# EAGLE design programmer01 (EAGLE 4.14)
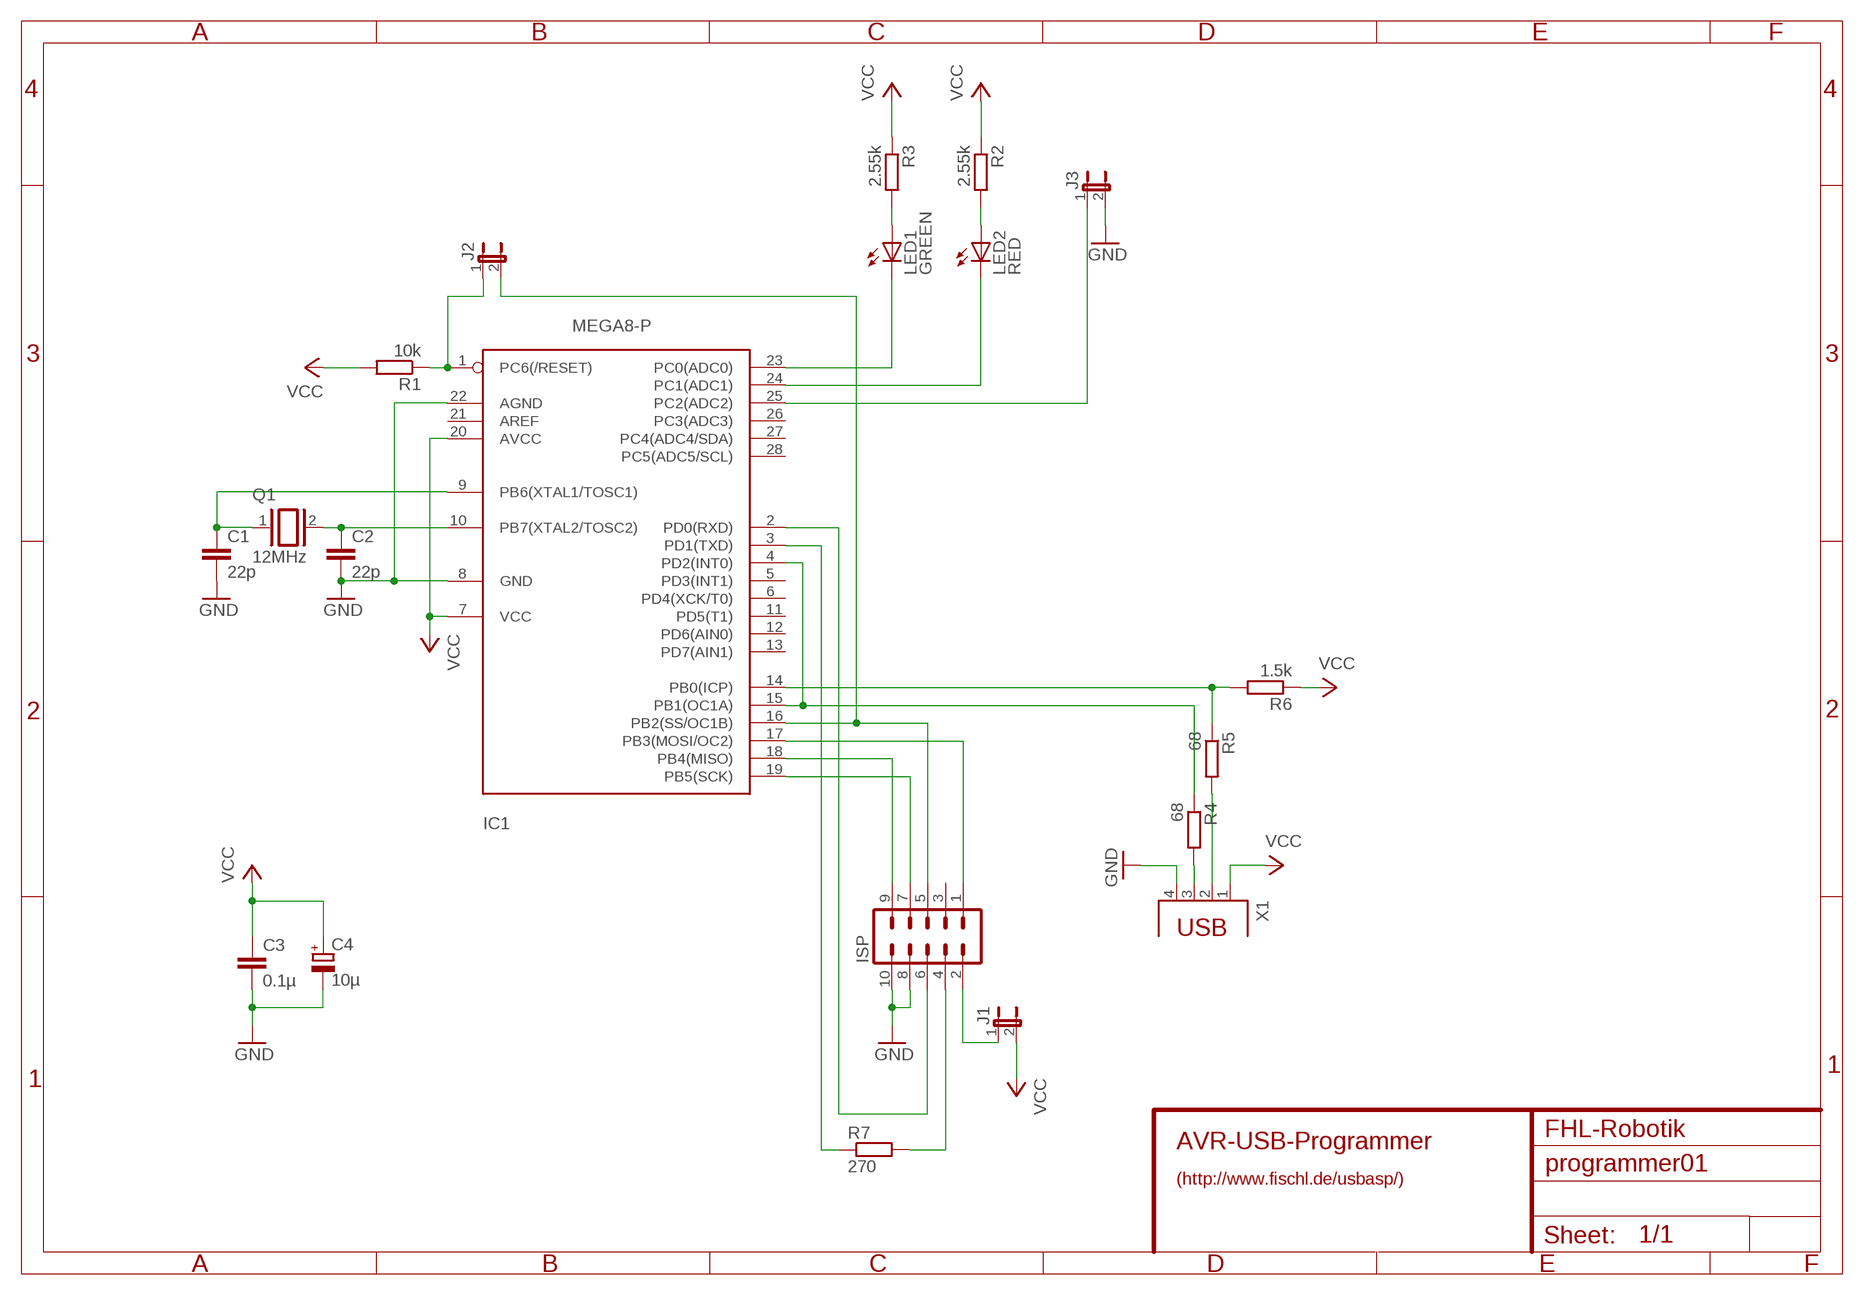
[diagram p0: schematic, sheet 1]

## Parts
C1  22p  C-EU025-025X050  [C025-025X050]
C2  22p  C-EU025-025X050  [C025-025X050]
C3  0.1µ  C-EU025-025X050  [C025-025X050]
C4  10µ  CPOL-EUE2.5-5  [E2,5-5]
IC1  MEGA8-P  [DIL28-3]
ISP  MA05-2  [MA05-2]
J1  JP1E  [JP1]
J2  JP1E  [JP1]
J3  JP1E  [JP1]
LED1  GREEN  LED3MM  [LED3MM]
LED2  RED  LED3MM  [LED3MM]
Q1  12MHz  XTAL/S  [QS]
R1  10k  R-EU_0207/7  [0207/7]
R2  2.55k  R-EU_0207/7  [0207/7]
R3  2.55k  R-EU_0207/7  [0207/7]
R4  68  R-EU_0207/7  [0207/7]
R5  68  R-EU_0207/7  [0207/7]
R6  1.5k  R-EU_0207/7  [0207/7]
R7  270  R-EU_0207/7  [0207/7]
X1  PN61729  [PN61729]

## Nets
GND: C1.2 C2.2 C3.2 C4.- IC1.8(GND) IC1.22(AGND) ISP.8 ISP.10 J3.2 X1.4
N$1: C2.1 IC1.10(PB7(XTAL2/TOSC2)) Q1.2
N$2: C1.1 IC1.9(PB6(XTAL1/TOSC1)) Q1.1
N$3: IC1.1(PC6(/RESET)) J2.1 R1.1
N$4: IC1.16(PB2(SS/OC1B)) ISP.5 J2.2
N$5: IC1.24(PC1(ADC1)) LED2.K(C)
N$6: LED2.A R2.2
N$7: LED1.A R3.2
N$8: IC1.23(PC0(ADC0)) LED1.K(C)
N$9: IC1.4(PD2(INT0)) IC1.15(PB1(OC1A)) R4.1
N$10: R4.2 X1.3
N$11: R5.2 X1.2
N$12: IC1.14(PB0(ICP)) R5.1 R6.2
N$13: IC1.25(PC2(ADC2)) J3.1
N$14: IC1.17(PB3(MOSI/OC2)) ISP.1
N$15: IC1.19(PB5(SCK)) ISP.7
N$16: IC1.18(PB4(MISO)) ISP.9
N$17: ISP.2 J1.1
N$19: IC1.3(PD1(TXD)) R7.1
N$21: IC1.2(PD0(RXD)) ISP.6
N$22: ISP.4 R7.2
VCC: C3.1 C4.+ IC1.7(VCC) IC1.20(AVCC) J1.2 R1.2 R2.1 R3.1 R6.1 X1.1
Unconnected: IC1.5(PD3(INT1)) IC1.6(PD4(XCK/T0)) IC1.11(PD5(T1)) IC1.12(PD6(AIN0)) IC1.13(PD7(AIN1)) IC1.21(AREF) IC1.26(PC3(ADC3)) IC1.27(PC4(ADC4/SDA)) IC1.28(PC5(ADC5/SCL)) ISP.3

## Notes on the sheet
- FHL-Robotik
- AVR-USB-Programmer
- (http://www.fischl.de/usbasp/)

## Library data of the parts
C1-C3 = rcl:C-EU: CAPACITOR, European symbol
C4 = rcl:CPOL-EU: POLARIZED CAPACITOR, European symbol
IC1 = avr:MEGA8-P: MICROCONTROLLER 8 Kbytes FLASH 1 kbytes SRAM 512 bytes EEPROM USART 4-channel 10 bit ADC 2-channel 8 bit ADC
ISP = con-lstb:MA05-2: PIN HEADER
J1-J3 = jumper:JP1E: JUMPER
LED1 LED2 = led:LED: LED
Q1 = special:XTAL/S: CRYSTAL
R1-R7 = rcl:R-EU_: RESISTOR, European symbol
X1 = con-berg:PN61729: BERG USB connector

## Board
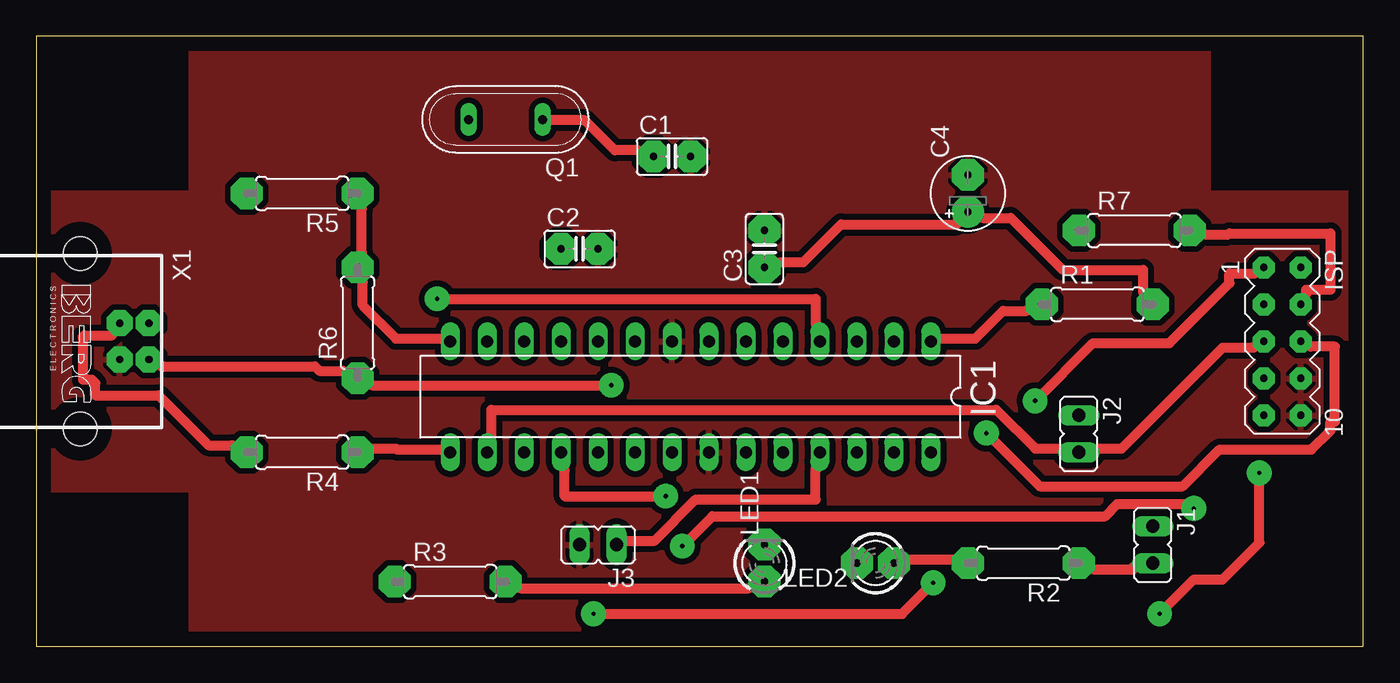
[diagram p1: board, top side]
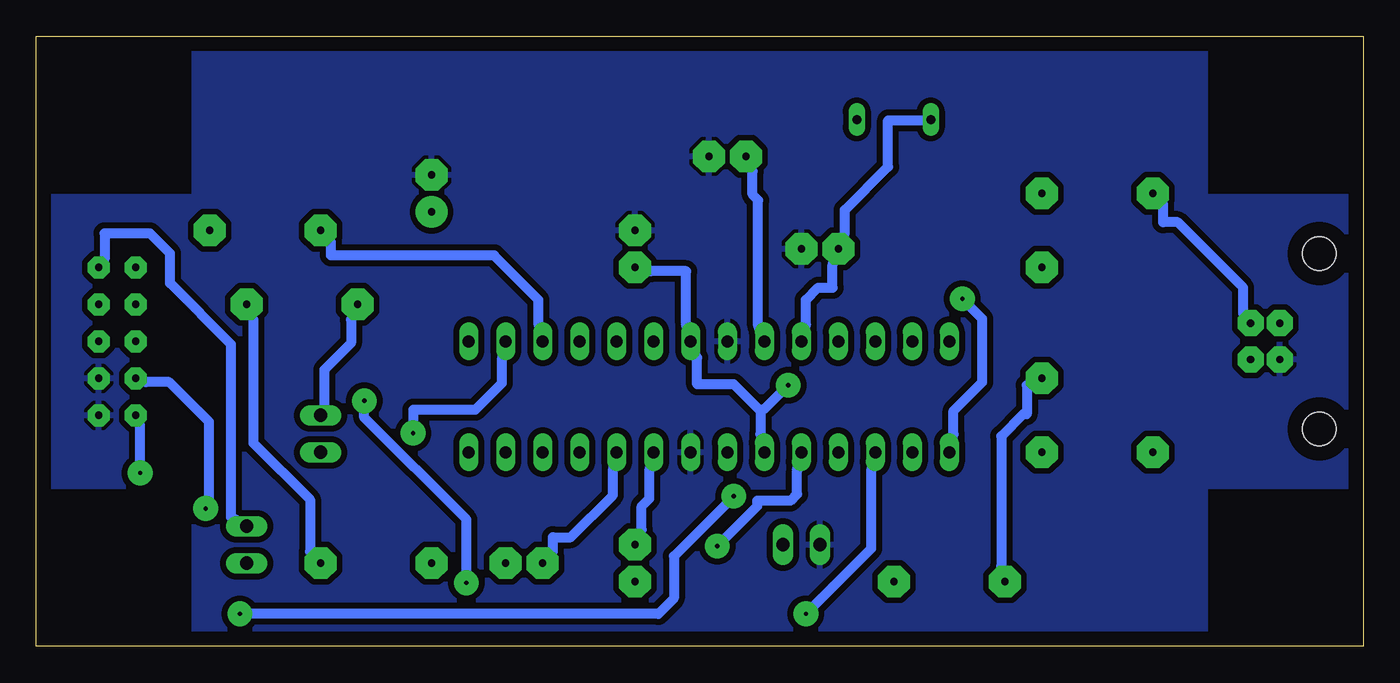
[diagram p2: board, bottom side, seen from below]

Size 91.11 x 41.9 mm. Coordinates in mm from the lower left corner, seen from the top.
Outline: 0,0 91.11,0 91.11,41.9 0,41.9 0,0
Copper layers (1*16): Top 0.035mm / dielectric 1.5mm / Bottom 0.035mm
Design rules "default": minimum track width 0.7mm, minimum drill 0.3mm, track to track 0.4mm, track to pad 0.4mm, pad to pad 0.4mm, via to via 0.4mm, smd to smd 0.4mm, copper to edge 40mil, drill to drill 8mil, minimum pad ring 10mil, minimum via ring 0.7mm, stop-mask expansion 4mil, vias tented up to drill 0mil, thermal gap 10mil
bRestrict: area 0.5,0.6 to 10.6,10.8; area 80.5,0.6 to 90.6,10.8; area 80.5,31.1 to 90.6,41.3; area 0.5,31.1 to 10.6,41.3

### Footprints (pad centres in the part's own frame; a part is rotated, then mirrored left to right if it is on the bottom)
C025-025X050 = drill 0.5 pad 2.18 octagon: 1 -1.27,0; 2 1.27,0
E2,5-5 = drill 0.5 pad 2.18 round: + -1.27,0 | drill 0.5 pad 2.18 octagon: - 1.27,0
DIL28-3 = drill 0.813 long: 1 -16.51,-3.81; 2 -13.97,-3.81; 3 -11.43,-3.81; 4 -8.89,-3.81; 5 -6.35,-3.81; 6 -3.81,-3.81; 7 -1.27,-3.81; 8 1.27,-3.81; 9 3.81,-3.81; 10 6.35,-3.81; 11 8.89,-3.81; 12 11.43,-3.81; 13 13.97,-3.81; 14 16.51,-3.81; 15 16.51,3.81; 16 13.97,3.81; 17 11.43,3.81; 18 8.89,3.81; 19 6.35,3.81; 20 3.81,3.81; 21 1.27,3.81; 22 -1.27,3.81; 23 -3.81,3.81; 24 -6.35,3.81; 25 -8.89,3.81; 26 -11.43,3.81; 27 -13.97,3.81; 28 -16.51,3.81
MA05-2 = drill 0.5 pad 1.5 octagon: 1 -5.08,-1.27; 2 -5.08,1.27; 3 -2.54,-1.27; 4 -2.54,1.27; 5 0,-1.27; 6 0,1.27; 7 2.54,-1.27; 8 2.54,1.27; 9 5.08,-1.27; 10 5.08,1.27
JP1 = drill 0.914 long: 1 0,-1.27; 2 0,1.27
LED3MM = drill 0.5 pad 2.184 octagon: A -1.27,0; K 1.27,0
QS = drill 0.61 long: 1 -2.54,0; 2 2.54,0
0207/7 = drill 0.5 pad 2.18 octagon: 1 -3.81,0; 2 3.81,0
PN61729 = drill 0.5 pad 1.8 octagon: 1 1.25,4.71; 2 -1.25,4.71; 3 -1.25,2.71; 4 1.25,2.71 | hole 2.3: -6.02,0; 6.02,0

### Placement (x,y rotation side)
C1  43.65,33.65 0 top
C2  37.3,27.3 0 top
C3  50,27.3 90 top
C4  63.97,31.11 90 top
IC1  44.92,17.14 180 top
ISP  85.56,20.95 270 top
J1  76.67,6.98 180 top
J2  71.59,14.6 180 top
J3  38.57,6.98 90 top
LED1  50,5.71 90 top
LED2  57.62,5.71 180 top
Q1  32.22,36.19 180 top
R1  72.86,23.49 0 top
R2  67.78,5.71 180 top
R3  28.41,4.44 0 top
R4  18.25,13.33 180 top
R5  18.25,31.11 180 top
R6  22.06,22.22 90 top
R7  75.4,28.57 0 top
X1  3.01,20.95 270 top

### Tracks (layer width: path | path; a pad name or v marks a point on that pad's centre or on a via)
GND
  pour Top: 0.47,10.79 10.63,10.79 10.63,0.63 80.48,0.63 80.48,10.79 90.64,10.79 90.64,31.11 80.48,31.11 80.48,41.27 10.63,41.27 10.63,31.11 0.47,31.11
  pour Bottom: 0.47,31.11 10.63,31.11 10.63,41.27 80.48,41.27 80.48,31.11 90.64,31.11 90.64,10.79 80.48,10.79 80.48,0.63 10.63,0.63 10.63,10.79 0.47,10.79
N$1
  Bottom 0.7: Q1.2 30.19,36.14 32.63,36.14 32.63,32.94 35.6,29.97 35.6,28.37 C2.1 36.44,26.23 36.44,24.63 37.43,24.63 38.27,23.79 38.27,22.2 IC1.10
N$2
  Top 0.7: Q1.1 35.29,36.14 37.66,36.14 39.71,34.08 41.31,34.08 C1.1
  Bottom 0.7: IC1.9 41.54,22.04 41.54,30.65 41.92,31.03 41.92,32.63 C1.1
N$3
  Top 0.7: IC1.1 62.04,21.13 64.48,21.13 66.38,23.03 67.98,23.03 R1.1
  Bottom 0.7: J2.1 71.34,16.56 71.34,18.99 69.51,20.82 69.51,22.42 R1.1
N$4
  Top 0.7: IC1.16 31.25,14.58 31.25,16.25 65.93,16.25 68.59,13.58 70.19,13.58 J2.2 72.94,13.58 74.54,13.58 81.47,20.52 83.6,20.52 83.6,20.59 ISP.5
N$5
  Bottom 0.7: IC1.24 51.52,12.06 51.52,10.38 54.42,7.49 55.64,7.49 55.64,6.5 LED2.K
N$6
  Top 0.7: R2.2 62.95,5.96 59.91,5.96 LED2.A
N$7
  Top 0.7: R3.2 33.24,3.98 48.93,3.98 LED1.A
N$8
  Bottom 0.7: IC1.23 49.01,12.06 49.01,10.16 49.54,9.62 49.54,8.02 LED1.K
N$9  (via drill 0.3)
  Top 0.7: IC1.15 27.83,13.51 24.78,13.51 24.7,13.58 23.1,13.58 R4.1 | v27.52,23.87 53.5,23.87 53.5,22.2 IC1.4
  Bottom 0.7: v27.52,23.87 26.15,22.5 26.15,18.16 28.13,16.18 28.13,14.58 IC1.15
N$10
  Top 0.7: X1.3 5.19,21.51 5.19,21.36 3.29,21.36 3.21,21.28 3.21,18.31 3.82,18.31 4.05,18.08 4.05,17.24 8.39,17.24 11.82,13.81 13.42,13.81 R4.2
N$11
  Bottom 0.7: X1.2 8.24,22.88 8.24,24.63 12.74,29.13 13.73,29.13 13.73,30.35 R5.2
N$12
  Top 0.7: IC1.14 27.83,21.13 24.7,21.13 22.42,23.41 22.42,25.01 R6.2 22.34,27.07 22.34,30.04 R5.1
N$13
  Top 0.7: IC1.25 53.5,12.06 53.5,10.08 45.28,10.08 42.46,7.26 40.48,7.26 J3.1
N$14  (via drill 0.3)
  Top 0.7: v38.27,2.23 59.45,2.23 v61.58,4.36 | v68.59,16.86 72.55,20.82 77.81,20.82 81.93,24.94 81.93,25.62 83.68,25.62 ISP.1
  Bottom 0.7: v38.27,2.23 33.77,6.73 33.77,12.06 IC1.17 | v61.58,4.36 61.58,8.71 68.59,15.72 v68.59,16.86
N$15  (via drill 0.3)
  Top 0.7: v44.36,6.88 46.42,8.94 73.39,8.94 74.23,9.77 79.19,9.77 v79.49,9.47
  Bottom 0.7: v44.36,6.88 41.62,9.62 41.62,10 39.33,10 38.88,10.46 38.88,12.06 IC1.19 | v79.49,9.47 79.34,9.47 79.34,9.54 79.26,9.62 79.26,15.41 82,18.16 83.6,18.16 ISP.7
N$16  (via drill 0.3)
  Top 0.7: v43.22,10.31 36.28,10.31 36.28,12.06 IC1.18 | v77.13,2.23 79.49,4.59 81.47,4.59 83.98,7.11 v83.98,11.91
  Bottom 0.7: v43.22,10.31 47.33,6.19 47.33,3.3 48.4,2.23 v77.13,2.23 | v83.98,11.91 83.98,15.18 ISP.9
N$17
  Bottom 0.7: J1.1 77.74,8.86 77.74,20.75 81.93,24.94 81.93,26.99 83.3,28.37 86.42,28.37 86.42,26.61 ISP.2
N$19
  Bottom 0.7: IC1.3 56.63,22.2 56.63,23.79 59.68,26.84 70.88,26.84 70.88,27.76 R7.1
N$21  (via drill 0.3)
  Top 0.7: v65.24,14.65 68.9,10.99 78.73,10.99 81.24,13.51 87.57,13.51 88.86,14.8 88.86,15.41 89.17,15.41 89.17,20.59 87.49,20.59 ISP.6
  Bottom 0.7: v65.24,14.65 65.24,16.25 60.97,16.25 59.14,18.08 59.14,19.68 IC1.2
N$22
  Top 0.7: ISP.4 87.19,24.18 87.19,24.48 88.86,24.48 88.86,28.37 81.93,28.37 81.85,28.29 80.25,28.29 R7.2
VCC  (via drill 0.3)
  Top 0.7: X1.1 8.55,19.3 8.55,19.22 19.14,19.22 19.44,18.92 21.04,18.92 R6.1 23.1,17.93 v39.48,17.93 | J1.2 75.3,5.43 75.3,5.28 72.63,5.28 R2.1 | C3.1 51.07,26.39 52.67,26.39 55.26,28.98 63.18,28.98 63.18,29.13 C4.+ 65.01,29.43 66.92,29.43 70.5,25.85 75.98,25.85 75.98,24.33 R1.2
  Bottom 0.7: R3.1 24.85,5.51 24.85,14.42 23.33,15.95 23.1,15.95 23.1,17.93 R6.1 | 41.39,16.18 41.39,14.58 IC1.20 | 41.39,16.18 43.22,18 45.73,18 45.73,19.83 IC1.7 46.49,22.2 46.49,25.78 48.93,25.78 C3.1 | R2.1 72.33,6.5 72.33,10.08 76.21,13.97 76.21,22.42 R1.2 | v39.48,17.93 41.09,16.33 41.39,16.18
